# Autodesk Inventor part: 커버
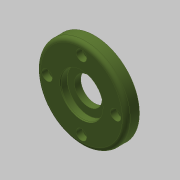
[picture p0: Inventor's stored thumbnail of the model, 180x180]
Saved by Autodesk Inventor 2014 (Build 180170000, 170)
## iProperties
Created: 2016-06
Part Number: 커버
Material: 알루미늄 6061
Document SubType Name: Modeling
Designer: mduedu
Density: 2.71 g/cm^3
Appearance: Olive Green
Author: mduedu
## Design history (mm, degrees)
sketch "스케치1"
  geometry: C1 r 34 at (0, 0); 1 further point
  constraints: 1 centre point, 1 coincident
  dimensions: "d0" = 68 diameter of C1
extrude "돌출1" new body sketch "스케치1" distance "d2" = 10; taper "d3" = 0 deg
sketch "스케치2"
  geometry: C1 r 21 at (0, 0); 1 further point
  constraints: 1 centre point, 1 coincident
  dimensions: "d4" = 42 diameter of C1
extrude "돌출2" join sketch "스케치2" distance "d6" = 3; taper "d7" = 0 deg
fillet "모깎기1" dims "d8" = 3
hole "구멍1" diameter "d11" = 35; stored, may be unused: countersink angle "d15" = 90 deg, drill point angle "d17" = 0 deg; dims "d9" = 10, "d10" = 10, "d12" = 6, "d13" = 4, "d14" = 2, "d16" = 3
hole "구멍2" diameter "d20" = 32; stored, may be unused: countersink angle "d24" = 90 deg, drill point angle "d26" = 0 deg; dims "d21" = 6, "d22" = 4, "d23" = 2, "d25" = 5.2, "d46" = 10, "d47" = 10
hole "구멍3" diameter "d29" = 21; stored, may be unused: countersink angle "d33" = 90 deg, drill point angle "d35" = 0 deg; dims "d27" = 10, "d28" = 10, "d30" = 6, "d31" = 4, "d32" = 2, "d34" = 5
fillet "모깎기2" dims "d36" = 3
fillet "모깎기3" dims "d37" = 0.1
chamfer "모따기1" distance "d38" = 0.75; stored, may be unused: second distance "d39" = 2, angle "d40" = 30 deg
chamfer "모따기2" distance "d42" = 0.5; stored, may be unused: second distance "d43" = 2, angle "d44" = 30 deg
sketch "스케치3" dims "d48" = 52
  geometry: 6 further points
  constraints: 2 vertical alignment, 1 coincident, 7 other
  dimensions: "d51" = 360 deg dimension on point (0, 0) point (0, 26) (derived)
sketch "스케치4"
  geometry: 4 further points
hole "구멍4" sketch "스케치4" at (0, 26), (-26, 0), (0, -26), (26, 0) diameter "d53" = 4.5; stored, may be unused: countersink angle "d57" = 90 deg, drill point angle "d59" = 0 deg; dims "d54" = 6, "d55" = 8, "d56" = 4.6, "d58" = 8
node "솔리드1"
